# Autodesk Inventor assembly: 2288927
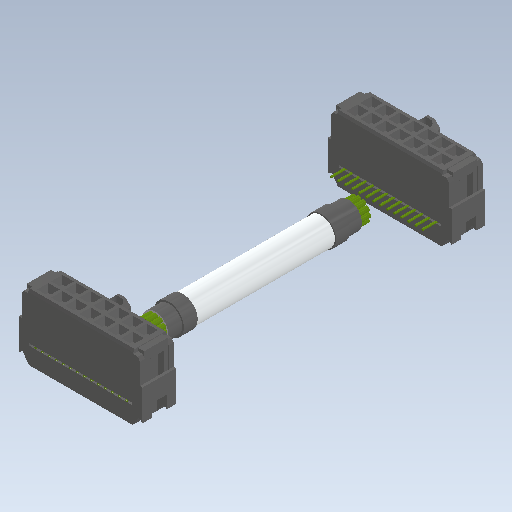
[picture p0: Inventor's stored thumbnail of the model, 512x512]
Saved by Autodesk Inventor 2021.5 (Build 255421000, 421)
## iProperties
Company: TraceParts S.A.
Created: 2026-04
Part Number: 2288927
Checked By: TraceParts S.A.
Catalog Web Link: www.traceparts.com
Document SubType Name: Assembly
Designer: TraceParts
Author: TraceParts
Sending System: TraceParts v2
Major Version: 6.0
Minor Version: 0.0
Format Version: 0.0
Product Id: TraceParts v2
REFERENCE: 2288927
SUPPLIER: PHOENIX CONTACT
ATT_0173_1_02_AAB654_010: True
ATT_0173_1_02_BAI969_008: 1.5
ATT_0173_1_02_AAT080_004: 14
ATT_0173_1_02_AAB651_010: True
ATT_0173_1_02_AAO663_005: 4017918057312
DESIGN: Cable
ATT_0173_1_02_AAB639_010: True
ATT_0173_1_02_AAB418_013: connector strip
ATT_0173_1_02_AAB643_010: True
ATT_0173_1_02_AAB419_013: connector strip
ATT_0173_1_02_BAC426_010: PLC other devices
TraceParts.PartVersion: 1.0.15
TraceParts.PartLanguage: en
TraceParts.PartNumber: 90-22022023-025659
TraceParts.InstanceId: 90-22022023-025659CZWA5CHYD9DJIT4REIRU7PTQ7
TraceParts.PartTitle: FLK 14/EZ-DR/ 150/KONFEK
TRACEPARTS: TRACEPARTS
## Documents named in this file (4)
- C:\TPO v2\SharedFS\Outgoing\2288927.iam
- C:\TPO v2\SharedFS\Outgoing\2288927_01.ipt
- C:\TPO v2\SharedFS\Outgoing\2288927_02.ipt
- C:\TPO v2\SharedFS\Outgoing\2288927_03.ipt
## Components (3 placed, 3 different names)
1. 2288927_Temp_1:1
2. 2288927_Temp_2:1
3. 2288927_Temp_3:1
